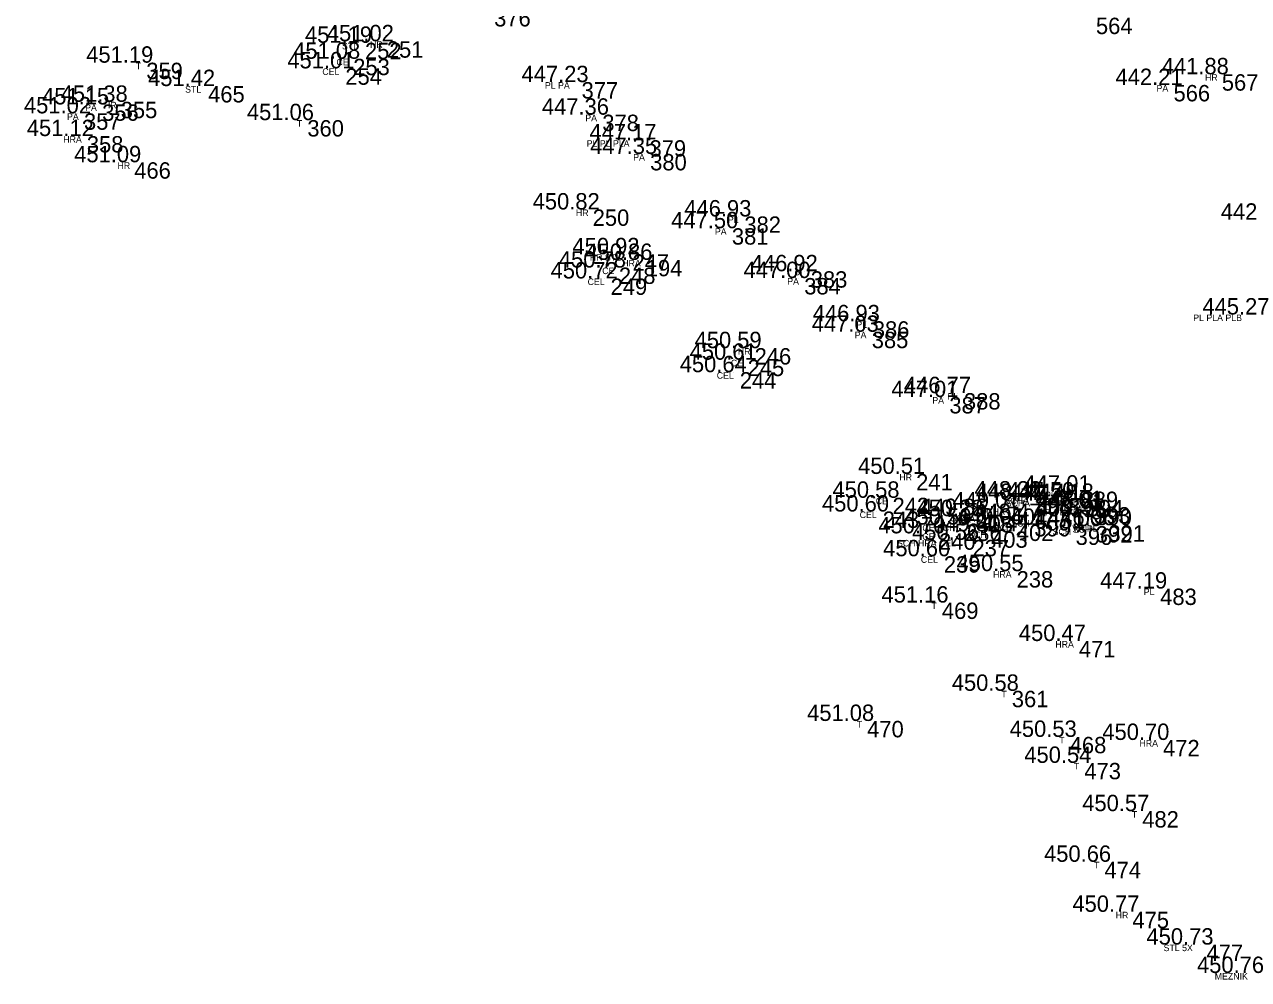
# Model space of a CAD drawing. Extents: x -639390 to -639075, y -1138747 to -1138358.
# Drawn here: x -639186.3 to -639130.3, y -1138740.7 to -1138697 of the extents above; entities that cross this region are included whole.
import ezdxf

# ---------------------------------------------------------------- set-up
doc = ezdxf.new("R2010")
doc.units = 0
for name, color, linetype in [('Vrstva 11', 7, 'Continuous'), ('Vrstva 12', 7, 'Continuous'), ('Vrstva 13', 7, 'Continuous'), ('Vrstva 57', 7, 'Continuous')]:
    doc.layers.add(name, color=color, linetype=linetype)

msp = doc.modelspace()

# ---------------------------------------------------------------- linework, layer by layer
at = {"layer": 'Vrstva 11'}
for p, q in [((-639170.97, -1138697.85), (-639170.97, -1138697.85)), ((-639169.97, -1138697.78), (-639169.97, -1138697.78)), ((-639180.98, -1138698.76), (-639180.98, -1138698.76)), ((-639171.51, -1138698.58), (-639171.51, -1138698.58)), ((-639171.87, -1138699.02), (-639171.87, -1138699.02)), ((-639131.76, -1138699.29), (-639131.76, -1138699.29)), ((-639178.15, -1138699.83), (-639178.15, -1138699.83)), ((-639161.06, -1138699.65), (-639161.06, -1138699.65)), ((-639133.97, -1138699.78), (-639133.97, -1138699.78)), ((-639182.15, -1138700.55), (-639182.15, -1138700.55)), ((-639183.83, -1138701.08), (-639183.83, -1138701.08)), ((-639183, -1138700.67), (-639183, -1138700.67)), ((-639173.61, -1138701.39), (-639173.61, -1138701.39)), ((-639160.11, -1138701.14), (-639160.11, -1138701.14)), ((-639183.7, -1138702.12), (-639183.7, -1138702.12)), ((-639157.95, -1138702.31), (-639157.95, -1138702.31)), ((-639181.53, -1138703.32), (-639181.53, -1138703.32)), ((-639157.92, -1138702.94), (-639157.92, -1138702.94)), ((-639160.55, -1138705.48), (-639160.55, -1138705.48)), ((-639153.61, -1138705.8), (-639153.61, -1138705.8)), ((-639154.18, -1138706.34), (-639154.18, -1138706.34)), ((-639158.73, -1138707.53), (-639158.73, -1138707.53)), ((-639158.12, -1138707.79), (-639158.12, -1138707.79)), ((-639159.35, -1138708.14), (-639159.35, -1138708.14)), ((-639150.57, -1138708.31), (-639150.57, -1138708.31)), ((-639159.73, -1138708.64), (-639159.73, -1138708.64)), ((-639150.87, -1138708.62), (-639150.87, -1138708.62)), ((-639147.73, -1138710.6), (-639147.73, -1138710.6)), ((-639147.78, -1138711.08), (-639147.78, -1138711.08)), ((-639153.14, -1138711.83), (-639153.14, -1138711.83)), ((-639153.46, -1138712.36), (-639153.46, -1138712.36)), ((-639153.82, -1138712.93), (-639153.82, -1138712.93)), ((-639143.56, -1138713.89), (-639143.56, -1138713.89)), ((-639144.23, -1138714.07), (-639144.23, -1138714.07)), ((-639145.75, -1138717.59), (-639145.75, -1138717.59)), ((-639138.18, -1138718.4), (-639138.18, -1138718.4)), ((-639146.83, -1138718.68), (-639146.83, -1138718.68)), ((-639140.33, -1138718.67), (-639140.33, -1138718.67)), ((-639140.27, -1138718.78), (-639140.27, -1138718.78)), ((-639138.8, -1138718.71), (-639138.8, -1138718.71)), ((-639138.69, -1138718.82), (-639138.69, -1138718.82)), ((-639137.94, -1138718.78), (-639137.94, -1138718.78)), ((-639147.28, -1138719.31), (-639147.28, -1138719.31)), ((-639142.99, -1138719.52), (-639142.99, -1138719.52)), ((-639142.79, -1138719.47), (-639142.79, -1138719.47)), ((-639141.43, -1138719.17), (-639141.43, -1138719.17)), ((-639137.62, -1138719.11), (-639137.62, -1138719.11)), ((-639137.55, -1138719.19), (-639137.55, -1138719.19)), ((-639143.51, -1138719.91), (-639143.51, -1138719.91)), ((-639141.14, -1138719.91), (-639141.14, -1138719.91)), ((-639140.34, -1138719.7), (-639140.34, -1138719.7)), ((-639138.45, -1138720.09), (-639138.45, -1138720.09)), ((-639137.53, -1138719.98), (-639137.53, -1138719.98)), ((-639136.95, -1138719.94), (-639136.95, -1138719.94)), ((-639144.7, -1138720.31), (-639144.7, -1138720.31)), ((-639143.17, -1138720.61), (-639143.17, -1138720.61)), ((-639142.32, -1138720.22), (-639142.32, -1138720.22)), ((-639144.48, -1138721.36), (-639144.48, -1138721.36)), ((-639141.15, -1138722.04), (-639141.15, -1138722.04)), ((-639134.58, -1138722.84), (-639134.58, -1138722.84)), ((-639144.57, -1138723.48), (-639144.57, -1138723.48)), ((-639138.3, -1138725.24), (-639138.3, -1138725.24)), ((-639141.37, -1138727.52), (-639141.37, -1138727.52)), ((-639147.99, -1138728.9), (-639147.99, -1138728.9)), ((-639138.72, -1138729.63), (-639138.72, -1138729.63)), ((-639134.45, -1138729.77), (-639134.45, -1138729.77)), ((-639138.05, -1138730.82), (-639138.05, -1138730.82)), ((-639135.4, -1138733.03), (-639135.4, -1138733.03)), ((-639137.13, -1138735.35), (-639137.13, -1138735.35)), ((-639135.85, -1138737.64), (-639135.85, -1138737.64)), ((-639132.46, -1138739.14), (-639132.46, -1138739.14))]:
    msp.add_line(p, q, dxfattribs=at)

# ---------------------------------------------------------------- texts
at = {"layer": 'Vrstva 12'}
for s, p in [('451.19 ', (-639173.439, -1138697.85)), ('451.02 ', (-639172.439, -1138697.78)), ('451.19 ', (-639183.449, -1138698.76)), ('451.01 ', (-639174.245, -1138699.02)), ('451.08 ', (-639173.979, -1138698.58)), ('441.88 ', (-639134.229, -1138699.29)), ('451.42 ', (-639180.619, -1138699.83)), ('447.23 ', (-639163.529, -1138699.65)), ('442.21 ', (-639136.345, -1138699.78)), ('451.15 ', (-639185.47, -1138700.67)), ('451.38 ', (-639184.619, -1138700.55)), ('451.02 ', (-639186.299, -1138701.08)), ('447.36 ', (-639162.596, -1138701.14)), ('451.06 ', (-639176.096, -1138701.39)), ('451.12 ', (-639186.169, -1138702.12)), ('447.17 ', (-639160.419, -1138702.31)), ('447.35 ', (-639160.39, -1138702.94)), ('451.09 ', (-639183.999, -1138703.32)), ('450.82 ', (-639163.019, -1138705.48)), ('446.93 ', (-639156.079, -1138705.8)), ('447.50 ', (-639156.679, -1138706.34)), ('442.48 ', (-639131.529, -1138705.95)), ('450.92 ', (-639161.199, -1138707.53)), ('450.86 ', (-639160.606, -1138707.79)), ('450.78 ', (-639161.819, -1138708.14)), ('446.92 ', (-639153.039, -1138708.31)), ('450.72 ', (-639162.199, -1138708.64)), ('447.00 ', (-639153.369, -1138708.62)), ('446.93 ', (-639150.199, -1138710.6)), ('445.27 ', (-639132.369, -1138710.29)), ('447.03 ', (-639150.249, -1138711.08)), ('450.59 ', (-639155.609, -1138711.83)), ('450.61 ', (-639155.835, -1138712.36)), ('450.64 ', (-639156.289, -1138712.93)), ('447.01 ', (-639146.605, -1138714.07)), ('446.77 ', (-639146.029, -1138713.89)), ('450.51 ', (-639148.125, -1138717.59)), ('450.58 ', (-639149.299, -1138718.68)), ('448.33 ', (-639142.799, -1138718.67)), ('447.01 ', (-639140.555, -1138718.4)), ('449.01 ', (-639143.805, -1138719.17)), ('448.44 ', (-639142.739, -1138718.78)), ('447.50 ', (-639141.299, -1138718.71)), ('447.48 ', (-639141.159, -1138718.82)), ('447.18 ', (-639140.409, -1138718.78)), ('447.01 ', (-639139.995, -1138719.11)), ('446.91 ', (-639139.925, -1138719.19)), ('450.60 ', (-639149.779, -1138719.31)), ('450.28 ', (-639145.459, -1138719.52)), ('449.86 ', (-639145.276, -1138719.47)), ('448.47 ', (-639142.809, -1138719.7)), ('450.70 ', (-639147.199, -1138720.31)), ('450.50 ', (-639146.009, -1138719.91)), ('449.81 ', (-639144.695, -1138720.22)), ('449.05 ', (-639143.61, -1138719.91)), ('447.51 ', (-639140.825, -1138720.09)), ('447.00 ', (-639140.029, -1138719.98)), ('446.96 ', (-639139.436, -1138719.94)), ('450.56 ', (-639145.656, -1138720.61)), ('450.60 ', (-639146.979, -1138721.36)), ('450.55 ', (-639143.62, -1138722.04)), ('447.19 ', (-639137.049, -1138722.84)), ('451.16 ', (-639147.056, -1138723.48)), ('450.47 ', (-639140.769, -1138725.24)), ('450.58 ', (-639143.839, -1138727.52)), ('451.08 ', (-639150.459, -1138728.9)), ('450.53 ', (-639141.189, -1138729.63)), ('450.70 ', (-639136.949, -1138729.77)), ('450.54 ', (-639140.519, -1138730.82)), ('450.57 ', (-639137.869, -1138733.03)), ('450.66 ', (-639139.616, -1138735.35)), ('450.77 ', (-639138.319, -1138737.64)), ('450.73 ', (-639134.929, -1138739.14)), ('450.76 ', (-639132.616, -1138740.44))]:
    msp.add_text(s, height=0.75, dxfattribs=at).set_placement(p)
at = {"layer": 'Vrstva 13'}
for s, p in [(' 376', (-639165.06, -1138697.1)), (' 564', (-639137.52, -1138697.45)), (' 252', (-639170.97, -1138698.6)), (' 251', (-639169.97, -1138698.53)), (' 359', (-639180.98, -1138699.51)), (' 253', (-639171.51, -1138699.33)), (' 254', (-639171.87, -1138699.77)), (' 567', (-639131.76, -1138700.04)), (' 465', (-639178.15, -1138700.58)), (' 377', (-639161.06, -1138700.4)), (' 566', (-639133.97, -1138700.53)), (' 355', (-639182.15, -1138701.3)), (' 357', (-639183.83, -1138701.83)), (' 356', (-639183, -1138701.42)), (' 360', (-639173.61, -1138702.14)), (' 378', (-639160.11, -1138701.89)), (' 358', (-639183.7, -1138702.87)), (' 379', (-639157.95, -1138703.06)), (' 466', (-639181.53, -1138704.07)), (' 380', (-639157.92, -1138703.69)), (' 250', (-639160.55, -1138706.23)), (' 382', (-639153.61, -1138706.55)), (' 381', (-639154.18, -1138707.09)), (' 247', (-639158.73, -1138708.28)), (' 194', (-639158.12, -1138708.54)), (' 248', (-639159.35, -1138708.89)), (' 383', (-639150.57, -1138709.06)), (' 249', (-639159.73, -1138709.39)), (' 384', (-639150.87, -1138709.37)), (' 386', (-639147.73, -1138711.35)), (' 385', (-639147.78, -1138711.83)), (' 246', (-639153.14, -1138712.58)), (' 245', (-639153.46, -1138713.11)), (' 244', (-639153.82, -1138713.68)), (' 388', (-639143.56, -1138714.64)), (' 387', (-639144.23, -1138714.82)), (' 241', (-639145.75, -1138718.34)), (' 389', (-639138.18, -1138719.15)), (' 242', (-639146.83, -1138719.43)), (' 398', (-639140.33, -1138719.42)), (' 400', (-639140.27, -1138719.53)), (' 397', (-639138.8, -1138719.46)), (' 395', (-639138.69, -1138719.57)), (' 394', (-639137.94, -1138719.53)), (' 243', (-639147.28, -1138720.06)), (' 405', (-639142.99, -1138720.27)), (' 404', (-639142.79, -1138720.22)), (' 401', (-639141.43, -1138719.92)), (' 393', (-639137.62, -1138719.86)), (' 390', (-639137.55, -1138719.94)), (' 236', (-639143.51, -1138720.66)), (' 402', (-639141.14, -1138720.66)), (' 399', (-639140.34, -1138720.45)), (' 396', (-639138.45, -1138720.84)), (' 392', (-639137.53, -1138720.73)), (' 391', (-639136.95, -1138720.69)), (' 240', (-639144.7, -1138721.06)), (' 237', (-639143.17, -1138721.36)), (' 403', (-639142.32, -1138720.97)), (' 239', (-639144.48, -1138722.11)), (' 238', (-639141.15, -1138722.79)), (' 483', (-639134.58, -1138723.59)), (' 469', (-639144.57, -1138724.23)), (' 471', (-639138.3, -1138725.99)), (' 361', (-639141.37, -1138728.27)), (' 470', (-639147.99, -1138729.65)), (' 468', (-639138.72, -1138730.38)), (' 472', (-639134.45, -1138730.52)), (' 473', (-639138.05, -1138731.57)), (' 482', (-639135.4, -1138733.78)), (' 474', (-639137.13, -1138736.1)), (' 475', (-639135.85, -1138738.39)), (' 477', (-639132.46, -1138739.89))]:
    msp.add_text(s, height=0.75, dxfattribs=at).set_placement(p)
at = {"layer": 'Vrstva 57'}
for s, p in [('STL', (-639171.745, -1138698.15)), ('HR', (-639170.459, -1138698.08)), ('T', (-639181.18, -1138699.06)), ('CE', (-639171.998, -1138698.88)), ('CEL', (-639172.645, -1138699.32)), ('HR', (-639132.249, -1138699.59)), ('STL', (-639178.925, -1138700.13)), ('PL PA', (-639162.46, -1138699.95)), ('PA', (-639134.47, -1138700.08)), ('HR', (-639182.639, -1138700.85)), ('PA', (-639184.33, -1138701.38)), ('PA', (-639183.5, -1138700.97)), ('T', (-639173.81, -1138701.69)), ('PA', (-639160.61, -1138701.44)), ('HRA', (-639184.5, -1138702.42)), ('PL PL PLA', (-639160.55, -1138702.61)), ('HR', (-639182.019, -1138703.62)), ('PA', (-639158.42, -1138703.24)), ('HR', (-639161.039, -1138705.78)), ('PL', (-639154.085, -1138706.1)), ('PA', (-639154.68, -1138706.64)), ('HR STL', (-639160.405, -1138707.83)), ('HRA', (-639158.92, -1138708.09)), ('CE', (-639159.838, -1138708.44)), ('PL', (-639151.045, -1138708.61)), ('CEL', (-639160.505, -1138708.94)), ('PA', (-639151.37, -1138708.92)), ('PL', (-639148.205, -1138710.9)), ('PL PLA PLB', (-639132.789, -1138710.59)), ('PA', (-639148.28, -1138711.38)), ('HR', (-639153.629, -1138712.13)), ('CE', (-639153.948, -1138712.66)), ('CEL', (-639154.595, -1138713.23)), ('PL', (-639144.035, -1138714.19)), ('PA', (-639144.73, -1138714.37)), ('HR', (-639146.239, -1138717.89)), ('PL VR', (-639139.569, -1138718.7)), ('CE', (-639147.318, -1138718.98)), ('SCHA', (-639141.43, -1138718.97)), ('SCHA', (-639141.37, -1138719.08)), ('SCH', (-639139.575, -1138719.01)), ('ZA', (-639139.19, -1138719.12)), ('SCHA', (-639139.04, -1138719.08)), ('CEL', (-639148.055, -1138719.61)), ('SCHA', (-639143.89, -1138719.77)), ('ZA', (-639143.49, -1138719.82)), ('SCHA', (-639142.53, -1138719.47)), ('VR PL VR', (-639139.839, -1138719.49)), ('SCHA', (-639138.72, -1138719.41)), ('CE SCH', (-639145.185, -1138720.21)), ('SCH', (-639141.915, -1138720.21)), ('SCH', (-639141.115, -1138720)), ('SCH', (-639139.225, -1138720.39)), ('VR PL', (-639138.325, -1138720.24)), ('SCH', (-639138.305, -1138720.28)), ('SCH HRA CEL', (-639146.345, -1138720.91)), ('CE', (-639145.188, -1138720.61)), ('SCH', (-639143.095, -1138720.52)), ('CEL', (-639145.255, -1138721.66)), ('HRA', (-639141.95, -1138722.34)), ('PL', (-639135.055, -1138723.14)), ('T', (-639144.77, -1138723.78)), ('HRA', (-639139.1, -1138725.54)), ('T', (-639141.57, -1138727.82)), ('T', (-639148.19, -1138729.2)), ('T', (-639138.92, -1138729.93)), ('HRA', (-639135.25, -1138730.07)), ('T', (-639138.25, -1138731.12)), ('T', (-639135.6, -1138733.33)), ('T', (-639137.33, -1138735.65)), ('HR', (-639136.339, -1138737.94)), ('STL 5X', (-639134.147, -1138739.44)), ('MEZNIK', (-639131.805, -1138740.74))]:
    msp.add_text(s, height=0.3, dxfattribs=at).set_placement(p)

doc.saveas('drawing.dxf')
